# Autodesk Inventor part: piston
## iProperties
Created: 2002-03
Part Number: piston
Material: Par défaut
Document SubType Name: Modélisation
Designer: User
Control State: 0
Master: False
Checked Out: False
Shininess: 86.0
Length Units: 11269
Angle Units: 11279
Time Units: 11290
Mass Units: 11283
Length Display Precision: 3
Angle Display Precision: 2
Density: 0.0
Volumn: 0.0
Area: 0.0
PropertySet Name: Model Information
Author: User
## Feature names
1. Révolution1 [Revolution]
